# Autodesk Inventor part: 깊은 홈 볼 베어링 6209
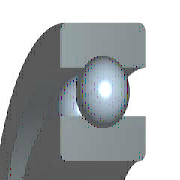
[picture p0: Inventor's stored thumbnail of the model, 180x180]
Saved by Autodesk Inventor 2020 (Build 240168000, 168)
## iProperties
IsCustomPart: 1
Created: 2012-02
Part Number: 깊은 홈 볼 베어링 6209
Material: 강철, 연강
Description: 깊은 그루부 볼 베어링
Document SubType Name: Modeling
Standard: JIS B 1521
Designer: mdu-01
Standards Organization: JIS
Language: ko-KR
Size Designation: 6209 45x85x19
Categories: <MemberInstance><Categories><Category DisplayName="샤프트 부품" InternalName="7f7aeb1f-a693-4053-b835-cee3144e0d98" Mnemonic="SHFT"><Category DisplayName="베어링" Inter
Density: 7.85 g/cm^3
Appearance: 강철(1)
Mass: 412.224 g
Surface Area: 242.591 cm^2
Volume: 52.5126 cm^3
Author: mdu-01
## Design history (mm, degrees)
sketch "스케치" dims "d0" = 10.4 (= -0.26 x WD + 0.26 x BD)
  geometry: L1 (4.3, 32.5)-(14.7, 32.5); L2 (9.5, 32.5)-(9.5, 27.3); L3 (9.5, 32.5)-(9.5, 37.7); L4 (5.636, 29.02)-(0, 29.02); L5 (0, 22.5)-(19, 22.5); L6 (5.636, 35.98)-(0, 35.98); L7 (0, 42.5)-(19, 42.5); L8 (19, 22.5)-(19, 29.02); L9 (13.364, 29.02)-(19, 29.02); L10 (13.364, 35.98)-(19, 35.98); L11 (19, 42.5)-(19, 35.98); L12 (-1.4, 0)-(8.4, 0) reference; L13 (0, -0.3)-(0, 5.3) reference
  constraints: 22 end point, 4 point on line, 2 collinear, 2 perpendicular, 2 symmetric about line, 1 midpoint, 1 parallel, 14 other
  dimensions: "d9" = 45 diameter of L5 L12 (= WD); "d11" = 85 diameter of L7 L12 (= BD); "d12" = 19 distance between parallel lines of L8 L13 (= KB); "d13" = 58.04 diameter of L9 L12 (= 0.326 x BD + 0.674 x WD)
revolve "본체" stored, may be unused: angle "d6" = 90 deg
revolve "볼" stored, may be unused: angle "d7" = 90 deg
pattern_circular "IDS_ARRAYBALL[SIMPL:T]" dims angle "d3" = 360 deg
body "Solid1"
fillet "모깎기1" dims "d1" = 1.1 (= KRS)
other parameters: "WD" = 45 [user parameter; used in 5 equation terms], "BD" = 85 [user parameter; used in 5 equation terms], "KB" = 19 [user parameter; used in 1 equation term], "KRS" = 1.1 [user parameter; used in 1 equation term], "d4" = 0, "d5" = 0, "d8" = 0, "d14" = 0, "d15" = 0, "BBA" = 0 [user parameter], "BC0" = 2.16e+07 [user parameter], "BC" = 3.32e+07 [user parameter], "BR" = 42.5 (= 0.5 x BD) [user parameter], "WR" = 22.5 (= 0.5 x WD) [user parameter]
